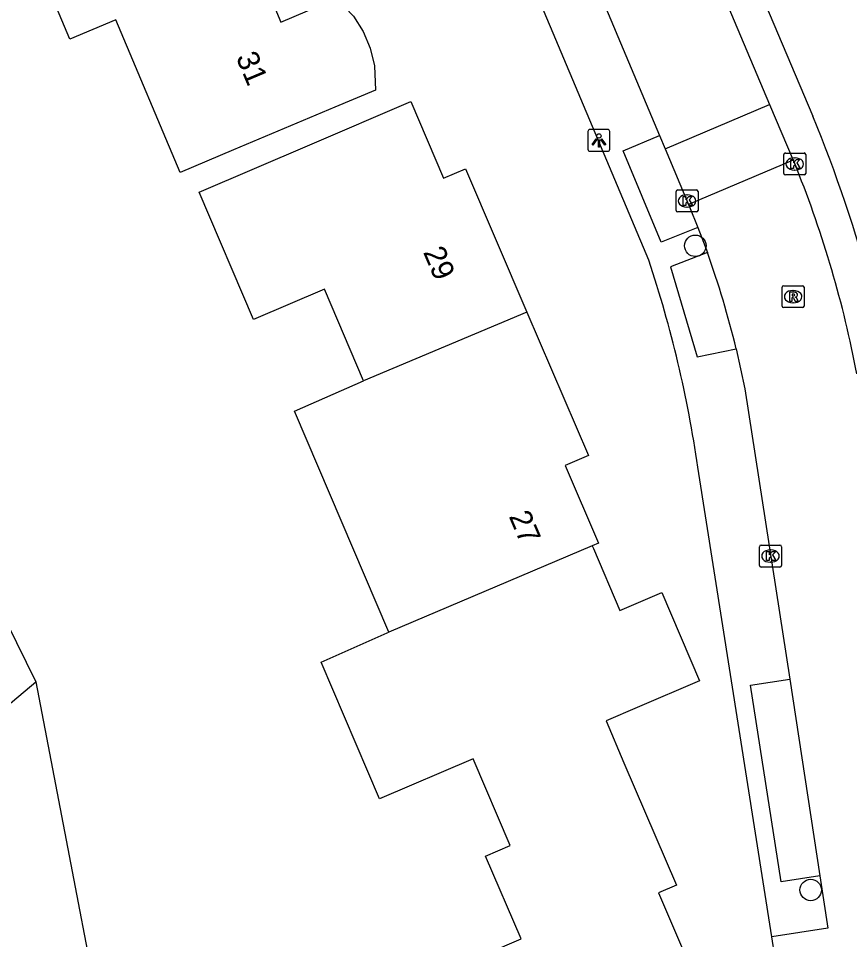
# Model space of a CAD drawing. Extents: x 158474 to 159560, y 388525 to 389605.
# Drawn here: x 158526.77 to 158564.62, y 389036.88 to 389078.81 of the extents above; entities that cross this region are included whole.
import ezdxf

# ---------------------------------------------------------------- set-up
doc = ezdxf.new("R2010")
doc.units = 0
for name, color, linetype in [('IMGEO_Boom', 7, 'Continuous'), ('IMGEO_Greppel_droge_sloot', 7, 'Continuous'), ('IMGEO_Groenvoorziening', 7, 'Continuous'), ('IMGEO_Hek', 7, 'Continuous'), ('IMGEO_Kolk', 7, 'Continuous'), ('IMGEO_Lichtpunt', 7, 'Continuous'), ('IMGEO_Pand', 7, 'Continuous'), ('IMGEO_Pand_nummerreeks', 7, 'Continuous'), ('IMGEO_Rijbaan_lokaal_open', 7, 'Continuous'), ('IMGEO_Rioolput', 7, 'Continuous'), ('IMGEO_Voetpad_open', 7, 'Continuous')]:
    doc.layers.add(name, color=color, linetype=linetype)

msp = doc.modelspace()

# ---------------------------------------------------------------- linework, layer by layer
at = {"layer": 'IMGEO_Boom'}
for centre in [(158557.592, 389068.464), (158562.844, 389039.142)]:
    msp.add_circle(centre, 0.489, dxfattribs=at)
at = {"layer": 'IMGEO_Greppel_droge_sloot'}
for points in [[(158502.141, 389112.903), (158501.952, 389108.465), (158502.035, 389106.941), (158502.367, 389105.452), (158514.242, 389075.687), (158527.566, 389048.61)], [(158525.906, 389047.243), (158527.566, 389048.61)]]:
    msp.add_lwpolyline(points, dxfattribs=at)
at = {"layer": 'IMGEO_Groenvoorziening'}
msp.add_lwpolyline([(158527.566, 389048.61), (158531.766, 389026.678)], dxfattribs=at)
at = {"layer": 'IMGEO_Hek'}
msp.add_lwpolyline([(158527.566, 389048.61), (158531.766, 389026.678)], dxfattribs=at)
at = {"layer": 'IMGEO_Kolk'}
for p, q in [((158561.618, 389071.761), (158561.618, 389072.613)), ((158561.693, 389072.687), (158562.545, 389072.687)), ((158562.106, 389072.467), (158562.131, 389072.467)), ((158562.619, 389072.613), (158562.619, 389071.761)), ((158562.545, 389071.687), (158561.693, 389071.687)), ((158562.129, 389071.907), (158562.104, 389071.907)), ((158556.717, 389070.077), (158556.717, 389070.929)), ((158556.792, 389071.003), (158557.644, 389071.003)), ((158557.205, 389070.783), (158557.23, 389070.783)), ((158557.718, 389070.929), (158557.718, 389070.077)), ((158557.644, 389070.003), (158556.792, 389070.003)), ((158557.228, 389070.223), (158557.203, 389070.223)), ((158560.589, 389054.842), (158561.441, 389054.842)), ((158560.514, 389053.916), (158560.514, 389054.768)), ((158561.002, 389054.622), (158561.027, 389054.622)), ((158561.515, 389054.768), (158561.515, 389053.916)), ((158561.025, 389054.062), (158561, 389054.062)), ((158561.441, 389053.842), (158560.589, 389053.842))]:
    msp.add_line(p, q, dxfattribs=at)
for points in [[(158561.618, 389071.761), (158561.618, 389072.613)], [(158561.693, 389072.687), (158562.545, 389072.687)], [(158562.619, 389072.613), (158562.619, 389071.761)], [(158561.939, 389072.387), (158562.062, 389072.387), (158562.062, 389072.236), (158562.192, 389072.387), (158562.356, 389072.387), (158562.21, 389072.236), (158562.363, 389071.987), (158562.211, 389071.987), (158562.126, 389072.151), (158562.062, 389072.084), (158562.062, 389071.987), (158561.939, 389071.987), (158561.939, 389072.387)], [(158562.545, 389071.687), (158561.693, 389071.687)], [(158556.717, 389070.077), (158556.717, 389070.929)], [(158556.792, 389071.003), (158557.644, 389071.003)], [(158557.718, 389070.929), (158557.718, 389070.077)], [(158557.038, 389070.703), (158557.161, 389070.703), (158557.161, 389070.552), (158557.291, 389070.703), (158557.455, 389070.703), (158557.309, 389070.552), (158557.462, 389070.303), (158557.31, 389070.303), (158557.225, 389070.467), (158557.161, 389070.4), (158557.161, 389070.303), (158557.038, 389070.303), (158557.038, 389070.703)], [(158557.644, 389070.003), (158556.792, 389070.003)], [(158560.589, 389054.842), (158561.441, 389054.842)], [(158560.514, 389053.916), (158560.514, 389054.768)], [(158560.835, 389054.542), (158560.958, 389054.542), (158560.958, 389054.391), (158561.088, 389054.542), (158561.252, 389054.542), (158561.106, 389054.391), (158561.259, 389054.142), (158561.107, 389054.142), (158561.022, 389054.306), (158560.958, 389054.239), (158560.958, 389054.142), (158560.835, 389054.142), (158560.835, 389054.542)], [(158561.515, 389054.768), (158561.515, 389053.916)], [(158561.441, 389053.842), (158560.589, 389053.842)]]:
    msp.add_lwpolyline(points, dxfattribs=at)
for centre, start, end in [((158561.695, 389072.611), 91.552, 178.448), ((158561.695, 389072.611), 91.552, 178.448), ((158562.543, 389072.611), 1.552, 88.448), ((158562.543, 389072.611), 1.552, 88.448), ((158561.695, 389071.763), 181.552, 268.448), ((158561.695, 389071.763), 181.552, 268.448), ((158562.543, 389071.763), 271.552, 358.448), ((158562.543, 389071.763), 271.552, 358.448), ((158556.794, 389070.927), 91.552, 178.448), ((158556.794, 389070.927), 91.552, 178.448), ((158557.642, 389070.927), 1.552, 88.448), ((158557.642, 389070.927), 1.552, 88.448), ((158556.794, 389070.079), 181.552, 268.448), ((158556.794, 389070.079), 181.552, 268.448), ((158557.642, 389070.079), 271.552, 358.448), ((158557.642, 389070.079), 271.552, 358.448), ((158560.591, 389054.766), 91.552, 178.448), ((158560.591, 389054.766), 91.552, 178.448), ((158561.439, 389054.766), 1.552, 88.448), ((158561.439, 389054.766), 1.552, 88.448), ((158560.591, 389053.918), 181.552, 268.448), ((158560.591, 389053.918), 181.552, 268.448), ((158561.439, 389053.918), 271.552, 358.448), ((158561.439, 389053.918), 271.552, 358.448)]:
    msp.add_arc(centre, 0.0765, start, end, dxfattribs=at)
for centre, major_axis, ratio, start_param, end_param in [((158562.105, 389072.187), (-0.387, 0.002), 0.722429, 4.712389, 7.853982), ((158562.13, 389072.187), (-0.39, 0.002), 0.717154, 1.570796, 4.712389), ((158557.204, 389070.503), (-0.387, 0.002), 0.722429, 4.712389, 7.853982), ((158557.229, 389070.503), (-0.39, 0.002), 0.717154, 1.570796, 4.712389), ((158561.001, 389054.342), (-0.387, 0.002), 0.722429, 4.712389, 7.853982), ((158561.026, 389054.342), (-0.39, 0.002), 0.717154, 1.570796, 4.712389)]:
    msp.add_ellipse(centre, major_axis=major_axis, ratio=ratio, start_param=start_param, end_param=end_param, dxfattribs=at)
at = {"layer": 'IMGEO_Lichtpunt'}
for p, q in [((158552.701, 389073.666), (158552.701, 389072.859)), ((158552.701, 389073.666), (158552.701, 389072.859)), ((158553.603, 389073.761), (158552.795, 389073.761)), ((158553.603, 389073.761), (158552.795, 389073.761)), ((158553.697, 389072.859), (158553.697, 389073.666)), ((158553.697, 389072.859), (158553.697, 389073.666)), ((158552.795, 389072.765), (158553.603, 389072.765)), ((158552.795, 389072.765), (158553.603, 389072.765))]:
    msp.add_line(p, q, dxfattribs=at)
for points in [[(158553.075, 389073.33), (158553.114, 389073.302), (158552.926, 389073.04), (158552.888, 389073.067), (158553.075, 389073.33)], [(158553.177, 389073.282), (158553.224, 389073.282), (158553.224, 389072.96), (158553.177, 389072.96), (158553.177, 389073.282)], [(158553.287, 389073.302), (158553.325, 389073.329), (158553.512, 389073.067), (158553.473, 389073.039), (158553.287, 389073.302)]]:
    msp.add_lwpolyline(points, dxfattribs=at)
msp.add_circle((158553.2, 389073.464), 0.0994, dxfattribs=at)
for centre, start, end in [((158552.795, 389073.666), 90, 180), ((158552.795, 389073.666), 90, 180), ((158553.603, 389073.666), 0, 90), ((158553.603, 389073.666), 0, 90), ((158552.795, 389072.859), 180, 270), ((158552.795, 389072.859), 180, 270), ((158553.603, 389072.859), 270, 0), ((158553.603, 389072.859), 270, 360)]:
    msp.add_arc(centre, 0.0946, start, end, dxfattribs=at)
at = {"layer": 'IMGEO_Pand'}
for points in [[(158543.967, 389089.109), (158546.242, 389083.711), (158538.744, 389080.551), (158538.045, 389080.257), (158538.723, 389078.647), (158541.248, 389079.73), (158542.024, 389078.916), (158542.472, 389078.21), (158542.792, 389077.459), (158542.978, 389076.652), (158543.028, 389075.553), (158541.178, 389074.774), (158536.571, 389072.832), (158534.139, 389071.807), (158531.213, 389078.75), (158529.119, 389077.868), (158527.336, 389082.101), (158539.36, 389087.168), (158543.967, 389089.109)], [(158542.488, 389062.32), (158540.702, 389066.491), (158537.476, 389065.109), (158534.997, 389070.898), (158540.045, 389073.06), (158544.641, 389075.028), (158546.132, 389071.545), (158547.13, 389071.972), (158549.925, 389065.446)], [(158549.925, 389065.446), (158542.488, 389062.32)], [(158549.925, 389065.446), (158552.722, 389058.914), (158551.668, 389058.463), (158553.183, 389054.923), (158552.9, 389054.803)], [(158543.635, 389050.882), (158539.341, 389060.935), (158542.488, 389062.32)], [(158552.9, 389054.803), (158552.95, 389054.687), (158554.162, 389051.857), (158556.07, 389052.675), (158557.787, 389048.667), (158554.94, 389047.448), (158553.526, 389046.842), (158554.342, 389044.936), (158556.73, 389039.361), (158555.91, 389039.01), (158557.73, 389034.76), (158544.614, 389029.143), (158542.583, 389033.884), (158546.521, 389035.571), (158549.66, 389036.915), (158548.045, 389040.687), (158549.165, 389041.167), (158547.473, 389045.119), (158543.214, 389043.295), (158540.555, 389049.505), (158543.564, 389050.852), (158543.635, 389050.882)], [(158552.9, 389054.803), (158543.635, 389050.882)]]:
    msp.add_lwpolyline(points, dxfattribs=at)
at = {"layer": 'IMGEO_Rijbaan_lokaal_open'}
for points in [[(158549.833, 389106.026), (158551.6, 389101.115), (158562.942, 389074.364)], [(158548.214, 389105.093), (158560.977, 389074.893)], [(158553.258, 389079.92), (158555.966, 389073.483)], [(158556.218, 389072.882), (158560.977, 389074.893)], [(158560.977, 389074.893), (158562.047, 389072.36)], [(158555.966, 389073.483), (158556.218, 389072.882)], [(158556.218, 389072.882), (158557.282, 389070.346)], [(158562.047, 389072.36), (158557.282, 389070.346)], [(158562.047, 389072.36), (158562.208, 389071.98)], [(158557.282, 389070.346), (158557.329, 389070.235), (158557.701, 389069.3)], [(158557.701, 389069.3), (158558.146, 389068.154)], [(158559.452, 389063.776), (158559.84, 389061.953), (158561.894, 389048.745)], [(158561.894, 389048.745), (158563.263, 389039.779)], [(158563.263, 389039.779), (158563.629, 389037.407), (158561.076, 389037.004)], [(158561.354, 389035.245), (158561.076, 389037.004)]]:
    msp.add_lwpolyline(points, dxfattribs=at)
for centre, radius, start, end in [((158505.178, 389050.505), 62.498, 7.04204, 22.44265), ((158515.205, 389053.126), 50.644, 10.8142, 21.8567), ((158516.794, 389053.435), 43.894, 13.6272, 19.5935)]:
    msp.add_arc(centre, radius, start, end, dxfattribs=at)
at = {"layer": 'IMGEO_Rioolput'}
for p, q in [((158561.545, 389065.722), (158561.545, 389066.574)), ((158561.62, 389066.648), (158562.472, 389066.648)), ((158562.546, 389066.574), (158562.546, 389065.722)), ((158562.033, 389066.428), (158562.058, 389066.428)), ((158562.056, 389065.868), (158562.031, 389065.868)), ((158562.472, 389065.648), (158561.62, 389065.648))]:
    msp.add_line(p, q, dxfattribs=at)
for points in [[(158561.545, 389065.722), (158561.545, 389066.574)], [(158561.62, 389066.648), (158562.472, 389066.648)], [(158562.546, 389066.574), (158562.546, 389065.722)], [(158562.134, 389066.346), (158561.882, 389066.348), (158561.882, 389065.948)], [(158561.882, 389065.948), (158562.006, 389065.948), (158562.006, 389066.11), (158562.017, 389066.11)], [(158562.06, 389066.267), (158562.006, 389066.267), (158562.006, 389066.186)], [(158562.006, 389066.186), (158562.058, 389066.186)], [(158562.064, 389066.081), (158562.135, 389065.948), (158562.275, 389065.948), (158562.21, 389066.074)], [(158562.472, 389065.648), (158561.62, 389065.648)]]:
    msp.add_lwpolyline(points, dxfattribs=at)
for centre, radius, start, end in [((158561.622, 389066.572), 0.0765, 91.552, 178.448), ((158561.622, 389066.572), 0.0765, 91.552, 178.448), ((158562.47, 389066.572), 0.0765, 1.552, 88.448), ((158562.47, 389066.572), 0.0765, 1.552, 88.448), ((158562.016, 389066.057), 0.0533, 26.0293, 88.6989), ((158562.042, 389066.375), 0.19, 274.7715, 282.9687), ((158562.066, 389066.171), 0.0964, 77.0061, 93.1865), ((158562.08, 389066.228), 0.0378, 276.6634, 79.6772), ((158562.133, 389066.236), 0.109, 350.3612, 89.416), ((158562.131, 389066.236), 0.112, 277.5842, 350.9817), ((158562.115, 389066.021), 0.108, 29.5134, 73.7905), ((158561.622, 389065.724), 0.0765, 181.552, 268.448), ((158561.622, 389065.724), 0.0765, 181.552, 268.448), ((158562.47, 389065.724), 0.0765, 271.552, 358.448), ((158562.47, 389065.724), 0.0765, 271.552, 358.448)]:
    msp.add_arc(centre, radius, start, end, dxfattribs=at)
for centre, major_axis, ratio, start_param, end_param in [((158562.032, 389066.148), (-0.387, 0.002), 0.722429, 4.712389, 7.853982), ((158562.057, 389066.148), (-0.39, 0.002), 0.717154, 1.570796, 4.712389)]:
    msp.add_ellipse(centre, major_axis=major_axis, ratio=ratio, start_param=start_param, end_param=end_param, dxfattribs=at)
at = {"layer": 'IMGEO_Voetpad_open'}
for points in [[(158555.471, 389067.802), (158541.712, 389100.476), (158541.415, 389101.08)], [(158557.701, 389069.3), (158556.044, 389068.624), (158554.307, 389072.792), (158555.966, 389073.483)], [(158558.146, 389068.154), (158556.464, 389067.503), (158557.682, 389063.415), (158559.452, 389063.776)], [(158561.076, 389037.004), (158557.702, 389058.383)], [(158563.263, 389039.779), (158561.494, 389039.516), (158560.106, 389048.467), (158561.894, 389048.745)]]:
    msp.add_lwpolyline(points, dxfattribs=at)
msp.add_arc((158505.258, 389050.935), 52.97, 8.0832, 18.568, dxfattribs=at)

# ---------------------------------------------------------------- texts
at = {"layer": 'IMGEO_Pand_nummerreeks'}
for s, rotation, p in [('31', 292.847, (158536.662, 389077.047)), ('29', 293.1827, (158545.187, 389068.177)), ('27', 293.1702, (158549.088, 389056.154))]:
    msp.add_text(s, height=1, rotation=rotation, dxfattribs=at).set_placement(p)

doc.saveas('drawing.dxf')
